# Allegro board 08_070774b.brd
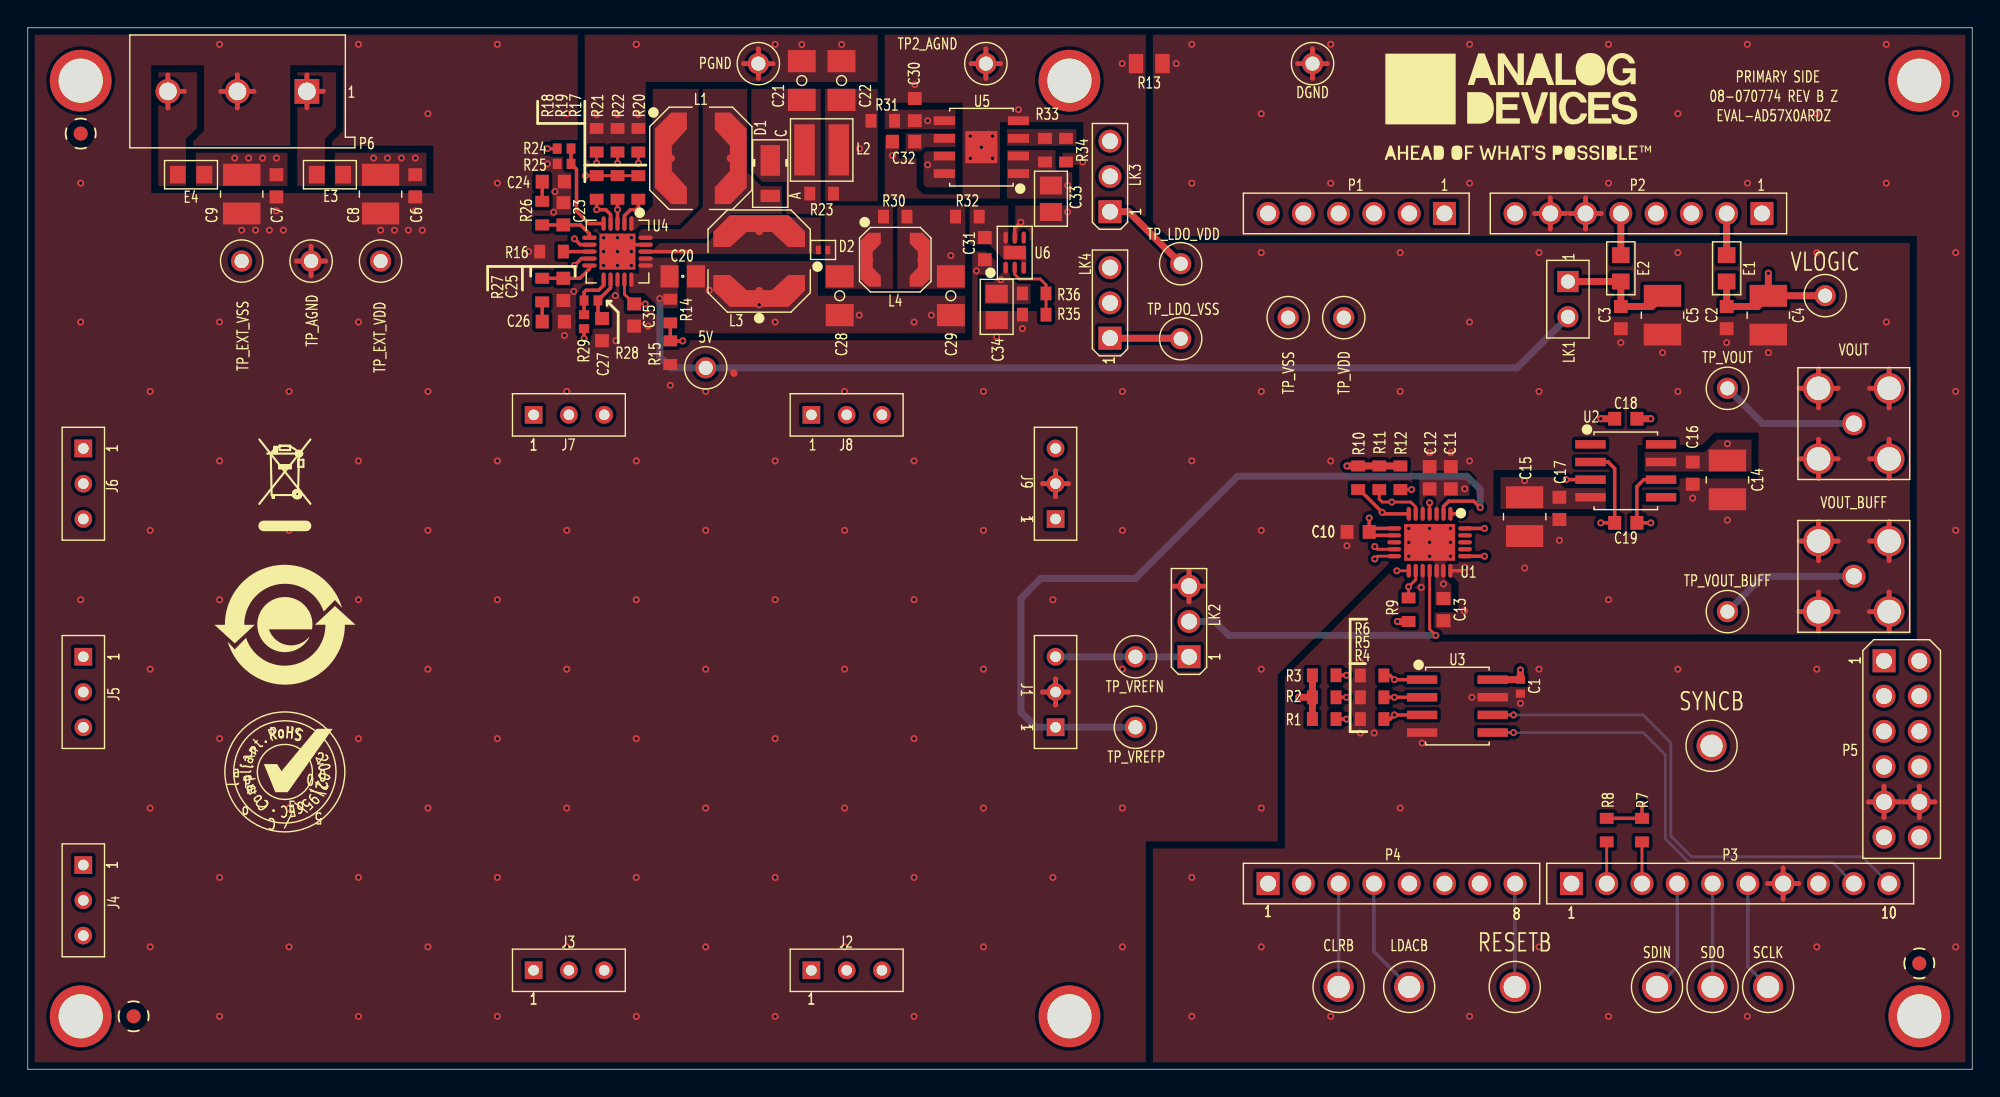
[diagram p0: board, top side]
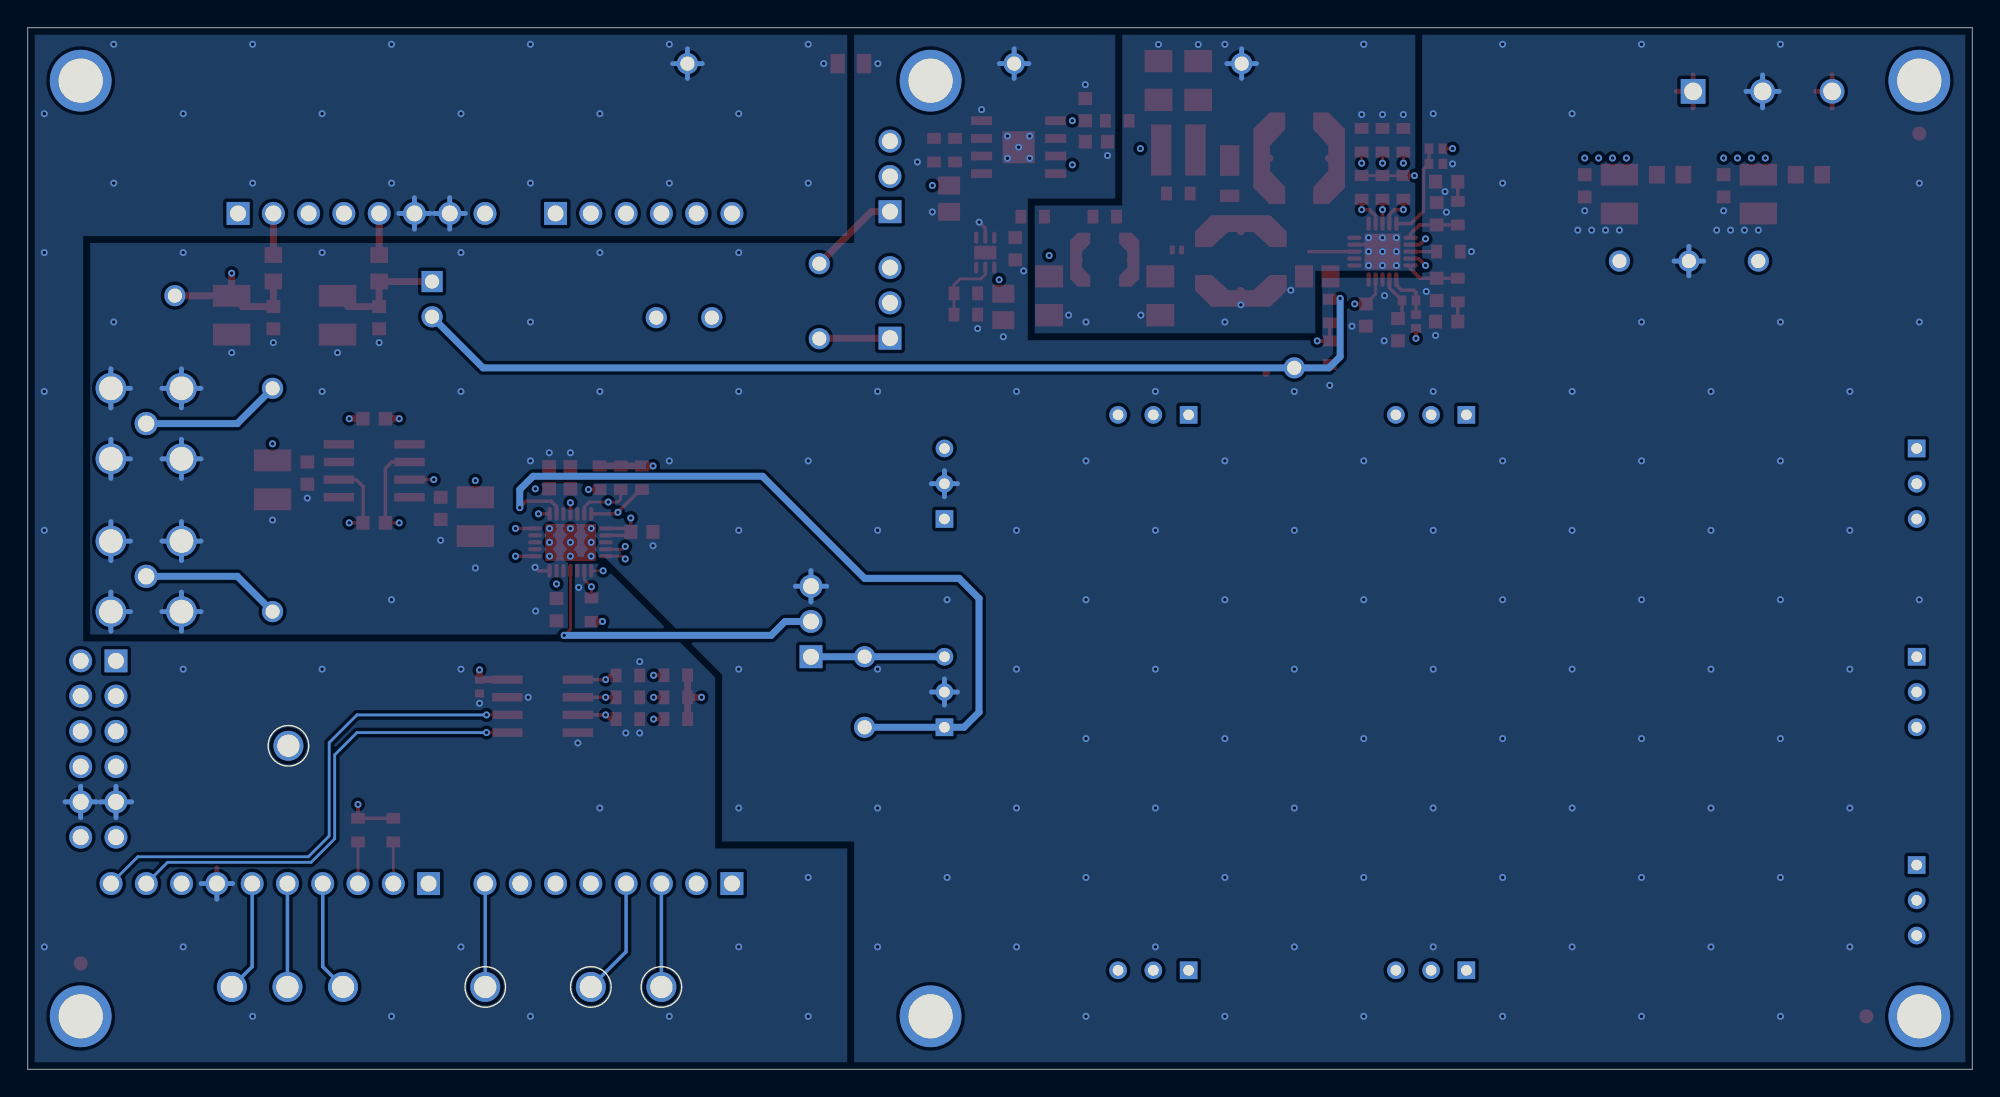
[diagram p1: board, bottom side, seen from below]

Outline 140 x 75 mm; copper layers: TOP, L2_GND, L3_SIG, L4_PWR, L5_GND, BOTTOM. Coordinates in mm from the lower left corner of the outline.
Outline path: 0,75 140,75 140,0 0,0 0,75

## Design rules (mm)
constraint set DEFAULT: 
net group POWER: nets AGND DGND VDD VSS

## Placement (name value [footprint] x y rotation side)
C1  0.1uF  [C0402]  107.47 27.55 90 top
C2  0.1uF  [C0603]  122.32 54.12 270 top
C3  0.1uF  [C0603]  114.7 54.12 270 top
C4  10uF  [C1210-2]  125.32 54.3 270 top
C5  10uF  [C1210-2]  117.7 54.3 270 top
C6  0.1uF  [C0603]  27.9 63.62 270 top
C7  0.1uF  [C0603]  17.9 63.62 270 top
C8  10uF  [C1210-2]  25.4 63.02 270 top
C9  10uF  [C1210-2]  15.4 63.02 270 top
C10  0.1uF  [C0603]  95.78 38.7 180 top
C11  0.1uF  [C0603]  102.46 42.59 90 top
C12  0.1uF  [C0603]  100.93 42.59 90 top
C13  0.1uF  [C0603]  101.93 33.09 270 top
C14  10uF  [C1210-2]  122.38 42.45 270 top
C15  10uF  [C1210-2]  107.78 39.79 90 top
C16  0.1uF  [C0603]  119.88 42.93 270 top
C17  0.1uF  [C0603]  110.28 40.39 90 top
C18  0.1uF  [C0603]  115.06 46.84 180 top
C19  10pF  [C0603]  115.06 39.34 180 top
C20  10uF  [C0805H60]  47.16 57.1 0 top
C21  4.7uF  [C1206H71]  55.73 71.2 90 top
C22  4.7uF  [C1206H71]  58.59 71.2 90 top
C23  27pF  [C0603]  38.56 61.6 90 top
C24  0.022uF  [C0603]  37.84 63.92 0 top
C25  22pF  [C0603]  38.56 56.16 270 top
C26  0.082uF  [C0603]  37.84 53.84 0 top
C27  1uF  [C0603]  41.34 53.26 270 top
C28  2.2uF  [C1206H71]  58.46 55.7 270 top
C29  2.2uF  [C1206H71]  66.46 55.7 270 top
C30  1uF  [C0603]  63.86 69.11 90 top
C31  1uF  [C0603]  68.9 59.09 270 top
C32  0.01uF  [C0603]  63.06 66.8 180 top
C33  2.2uF  [C0805H53]  73.67 62.69 270 top
C34  2.2uF  [C0805H53]  69.76 54.9 270 top
C35  1uF  [C0603]  43.66 54.31 270 top
CLRB  WHT  [CNKEY5005-9TP]  94.38 5.93 0 top
D1  DFLS130-7  [POWERDI123]  53.46 64.5 270 top
D2  BAT54LPS  [DFN2_1X0_6]  57.26 59 0 top
DGND  BLK  [CNKEY5001TP]  92.5 72.42 0 top
E1  600OHM  [L0805H50]  122.32 57.68 270 top
E2  600OHM  [L0805H50]  114.7 57.68 270 top
E3  600OHM  [L0805H50]  21.75 64.42 0 top
E4  600OHM  [L0805H50]  11.75 64.42 0 top
J1  350-10-103-00-006000  [CNTHMHDR1X3L300W100H284]  74 24.62 90 top
J2  310-13-103-41-001000  [CNTHFHDR1X3L300W100H165]  56.42 7.12 0 top
J3  310-13-103-41-001000  [CNTHFHDR1X3L300W100H165]  36.42 7.12 0 top
J4  350-10-103-00-006000  [CNTHMHDR1X3L300W100H284]  4 14.71 270 top
J5  310-13-103-41-001000  [CNTHFHDR1X3L300W100H165]  4 29.7 270 top
J6  310-13-103-41-001000  [CNTHFHDR1X3L300W100H165]  4 44.71 270 top
J7  310-13-103-41-001000  [CNTHFHDR1X3L300W100H165]  36.42 47.12 0 top
J8  350-10-103-00-006000  [CNTHMHDR1X3L300W100H284]  56.42 47.12 0 top
J9  310-13-103-41-001000  [CNTHFHDR1X3L300W100H165]  74 39.62 90 top
L1  15uH  [LSMSQ236H138]  48.46 65.6 0 top
L2  1.5uH  [LSMSQ157H83]  57.16 66.2 0 top
L3  6.8uH  [LSMSQ236H138]  52.66 58.2 90 top
L4  2.2UH  [LSMSQ154H71_A]  62.46 58.3 0 top
LDACB  WHT  [CNKEY5005-9TP]  99.46 5.93 0 top
LK1  69157-102HLF  [CNBERG69157-102]  110.89 56.73 270 top
LK2  TSW-103-08-G-S  [CNBERG1X3H205LD36]  83.61 29.7 90 top
LK3  TSW-103-08-G-S  [CNBERG1X3H205LD36]  77.92 61.76 90 top
LK4  TSW-103-08-G-S  [CNBERG1X3H205LD36]  77.92 52.65 90 top
NOREF  -  []  18.51 21.41 0 top
NOREF#2  -  []  18.51 32.01 0 top
NOREF#3  -  []  3.81 3.81 0 top
NOREF#4  -  []  140 75 0 top
NOREF#5  -  []  107.31 69.31 0 top
NOREF#6  -  []  15 -82 0 top
NOREF#7  -  [unnamed#2]  3.81 71.19 0 top
NOREF#8  -  []  15 -82 0 top
NOREF#9  -  []  140 0 0 top
NOREF#10  -  []  36.42 47.12 180 top
NOREF#11  -  [unnamed#2]  136.19 3.81 0 top
NOREF#12  -  []  88.21 167.82 0 top
NOREF#13  -  []  -2.99 312.45 0 top
NOREF#14  -  [unnamed#2]  3.81 67.38 0 top
NOREF#15  -  [unnamed#2]  3.81 3.81 0 top
NOREF#16  -  []  0 0 0 top
NOREF#17  -  []  76.21 73.31 0 top
NOREF#18  -  []  -22.36 -50.33 0 top
NOREF#19  -  []  -10.17 228.03 0 top
NOREF#20  -  []  212.02 314.24 0 top
NOREF#21  -  []  140 0 90 top
NOREF#22  -  [unnamed#2]  136.19 71.19 0 top
NOREF#23  -  [unnamed#2]  75 3.81 0 top
NOREF#24  -  []  -22.36 -50.33 0 top
NOREF#25  -  []  3.81 3.81 0 top
NOREF#26  -  []  134 13.37 180 top
NOREF#27  -  [unnamed#2]  75 71.19 0 top
NOREF#28  -  []  18.31 38.81 0 top
NOREF#29  -  []  76.75 90.75 0 top
NOREF#30  -  []  0 75 0 top
NOREF#31  -  [unnamed#2]  7.62 3.81 0 top
NOREF#32  -  []  140 0 0 top
NOREF#33  -  [unnamed#2]  136.19 7.62 0 top
P1  SSQ-106-03-G-S  [CNSAMTECSSQ-106-XX-X-S]  102 61.63 180 top
P2  SSQ-108-03-G-S  [CNSAMTECSSQ-108-XX-X-S]  124.86 61.63 180 top
P3  SSQ-110-03-G-S  [CNSAMTECSSQ-110-XX-X-S]  111.14 13.37 0 top
P4  SSQ-108-03-G-S  [CNSAMTECSSQ-108-XX-X-S]  89.3 13.37 0 top
P5  TSW-106-08-G-D  [CNHDR2X6H330LD35]  133.65 29.41 270 top
P6  8719  [CNKEYSTONE-8719]  20.1 70.42 180 top
PGND  BLK  [CNKEY5001TP]  52.6 72.42 0 top
R1  100K  [R0603]  93.34 25.21 0 top
R2  0  [R0603]  93.34 26.79 0 top
R3  0  [R0603]  93.34 28.37 0 top
R4  0  [R0603]  96.79 25.21 180 top
R5  100K  [R0603]  96.79 26.79 180 top
R6  100K  [R0603]  96.79 28.36 180 top
R7  0  [R0603]  116.22 17.22 90 top
R8  0  [R0603]  113.68 17.22 90 top
R9  10K  [R0603]  99.42 33.09 90 top
R10  10K  [R0603]  95.78 42.59 270 top
R11  10K  [R0603]  97.31 42.59 270 top
R12  10K  [R0603]  98.83 42.59 270 top
R13  0  [R0805]  80.74 72.42 180 top
R14  30.1K  [R0603]  46.26 54.6 90 top
R15  18.7K  [R0603]  46.26 51.6 90 top
R16  49.9K  [R0603]  37.71 58.88 0 top
R17  0  [R0603]  43.96 63.5 270 top
R18  0  [R0603]  40.96 63.5 270 top
R19  0  [R0603]  42.46 63.5 270 top
R20  0  [R0603]  43.96 66.9 90 top
R21  0  [R0603]  40.96 66.9 90 top
R22  0  [R0603]  42.46 66.9 90 top
R23  4.7  [R0603]  57.16 63.06 0 top
R24  63.4K  [R0402]  38.62 66.3 180 top
R25  3.57K  [R0402]  38.62 65.2 180 top
R26  22K  [R0603]  37.04 61.65 90 top
R27  30.1K  [R0603]  37.04 56.11 270 top
R28  2.8K  [R0402]  40.55 55.36 180 top
R29  54.9K  [R0402]  40.05 53.84 270 top
R30  10  [R0603]  62.46 61.4 0 top
R31  10  [R0603]  61.56 68.31 0 top
R32  10  [R0603]  67.65 61.4 0 top
R33  105K  [R0603]  73.24 66.19 90 top
R34  10K  [R0603]  74.75 66.19 270 top
R35  10K  [R0603]  72.46 54.34 0 top
R36  105K  [R0603]  72.46 55.87 180 top
RESETB  WHT  [CNKEY5005-9TP]  107.06 5.93 0 top
SCLK  WHT  [CNKEY5005-9TP]  125.3 5.93 0 top
SDIN  WHT  [CNKEY5005-9TP]  117.3 5.93 0 top
SDO  WHT  [CNKEY5005-9TP]  121.3 5.93 0 top
SYNCB  WHT  [CNKEY5005-9TP]  121.23 23.29 0 top
TP2_AGND  BLK  [CNKEY5001TP]  68.98 72.42 0 top
TP_AGND  BLK  [CNKEY5001TP]  20.4 58.2 0 top
TP_EXT_VDD  RED  [CNKEY5001TP]  25.4 58.2 0 top
TP_EXT_VSS  RED  [CNKEY5001TP]  15.4 58.2 0 top
TP_LDO_VDD  RED  [CNKEY5001TP]  83.01 58.01 0 top
TP_LDO_VSS  RED  [CNKEY5001TP]  83.01 52.61 0 top
TP_VDD  RED  [CNKEY5001TP]  94.75 54.12 0 top
TP_VOUT  RED  [CNKEY5001TP]  122.38 49.04 0 top
TP_VOUT_BUFF  RED  [CNKEY5001TP]  122.38 32.95 0 top
TP_VREFN  RED  [CNKEY5001TP]  79.75 29.7 0 top
TP_VREFP  RED  [CNKEY5001TP]  79.75 24.62 0 top
TP_VSS  RED  [CNKEY5001TP]  90.75 54.12 0 top
U1  AD5780BCPZ  [QFN24_5X4_PAD3_65X2_65]  100.93 37.95 180 top
U2  AD8675ARZ  [SO8]  115.06 43.09 270 top
U3  24AA32A-I/SN  [SO8]  102.93 26.15 270 top
U4  ADP5070ACPZ-R7  [QFN20_4X4_PAD2_6X2_6]  42.46 58.88 180 top
U5  ADP7118ARDZ  [SO8NB-PAD2_3X2_3]  68.66 66.4 90 top
U6  ADP7182ACPZN  [DFN6_2X2_PAD1_6X1]  71.06 58.81 0 top
UNK5V  RED  [CNKEY5001TP]  48.81 50.51 0 top
VLOGIC  RED  [CNKEY5001TP]  129.41 55.71 0 top
VOUT  131-3701-261  [CNJOHNSON131-3701-261]  131.47 46.5 0 top
VOUT_BUFF  131-3701-261  [CNJOHNSON131-3701-261]  131.47 35.49 0 top

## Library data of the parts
C1 = CAP: User Part Number: UPN; Tolerance: 10; alternate symbols: (C0402); part number: CAP_SM-0.1UF,16V,10,E028141,C0402; tolerance: 10
C2 C3 C6 C7 C10-C13 C16-C18 = CAP: User Part Number: UPN; Tolerance: 10; alternate symbols: (C0603); part number: CAP_SM-0.1UF,16V,10,E015036,C0603; tolerance: 10
C4 C5 C8 C9 C14 C15 = CAP: Tolerance: 10; User Part Number: UPN; alternate symbols: (C1210-2); part number: CAP_SM-10UF,50V,10,E022361,C1210-2; tolerance: 10
C19 = CAP: User Part Number: UPN; Tolerance: 0.5pF; alternate symbols: (C0603); part number: CAP_SM-10PF,50V,0.5PF,E016319,C0603; tolerance: 0.5pF
C20 = CAP: Tolerance: 10; User Part Number: UPN; alternate symbols: (C0805H60); part number: CAP_SM-10UF,25V,10,E026259,C0805H60; tolerance: 10
C21 C22 = CAP: Tolerance: 20; User Part Number: UPN; alternate symbols: (C1206H71); part number: CAP_SM-4.7UF,50V,20,E028522,C1206H71; tolerance: 20
C23 = CAP: User Part Number: UPN; Tolerance: 5; alternate symbols: (C0603); part number: CAP_SM-27PF,50V,5,E000395,C0603; tolerance: 5
C24 = CAP: User Part Number: UPN; Tolerance: 10; alternate symbols: (C0603); part number: CAP_SM-0.022UF,16V,10,E000327,C0603; tolerance: 10
C25 = CAP: User Part Number: UPN; Tolerance: 5; alternate symbols: (C0603); part number: CAP_SM-22PF,50V,5,E000411,C0603; tolerance: 5
C26 = CAP: User Part Number: UPN; Tolerance: 10; alternate symbols: (C0603); part number: CAP_SM-0.082UF,16V,10,E000332,C0603; tolerance: 10
C27 = CAP: User Part Number: UPN; Tolerance: 20; alternate symbols: (C0603); part number: CAP_SM-1UF,6.3V,20,E021364,C0603; tolerance: 20
C28 C29 = CAP: Tolerance: 10; User Part Number: UPN; alternate symbols: (C1206H71); part number: CAP_SM-2.2UF,50V,10,E033575,C1206H71; tolerance: 10
C30 C31 = CAP: User Part Number: UPN; Tolerance: 10; alternate symbols: (C0603); part number: CAP_SM-1UF,16V,10,E020596,C0603; tolerance: 10
C32 = CAP: User Part Number: UPN; Tolerance: 10; alternate symbols: (C0603); part number: CAP_SM-0.01UF,50V,10,E015579,C0603; tolerance: 10
C33 C34 = CAP: Tolerance: 10; User Part Number: UPN; alternate symbols: (C0805H53); part number: CAP_SM-2.2UF,25V,10,E025703,C0805H53; tolerance: 10
C35 = CAP: User Part Number: UPN; Tolerance: 10; alternate symbols: (C0603); part number: CAP_SM-1UF,16V,10,E025399,C0603; tolerance: 10
CLRB LDACB RESETB SCLK SDIN SDO SYNCB = CNTP1P: Tolerance: N/A; User Part Number: UPN; alternate symbols: (CNKEY5005-9TP); part number: CNTP1P_TH-WHT,E025331,CNKEY5005-9TP; tolerance: N/A
D1 = DIOSCHOTTKY: User Part Number: UPN; Tolerance: N/A; alternate symbols: (POWERDI123); part number: DIOSCHOTTKY_SM-DFLS130-7,30V,N/A,E026485,POWERDI123; tolerance: N/A
D2 = DIOSCHOTTKY: Tolerance: N/A; User Part Number: UPN; alternate symbols: (DFN2_1X0_6); part number: DIOSCHOTTKY_SM-BAT54LPS,30V,N/A,E023691,DFN2_1X0_6; tolerance: N/A
DGND PGND TP2_AGND TP_AGND = CNTP1P: Tolerance: N/A; User Part Number: UPN; alternate symbols: (CNKEY5001TP); part number: CNTP1P_TH-BLK,E005347,CNKEY5001TP; tolerance: N/A
E1-E4 = FERRITE: Tolerance: 25; User Part Number: UPN; alternate symbols: (L0805H50); part number: FERRITE_SM-600OHM,25,E013538,L0805H50; tolerance: 25
J1 J4 J8 = CN3P: User Part Number: UPN; Tolerance: N/A; alternate symbols: (CNTHMHDR1X3L300W100H284); part number: CN3P_TH-350-10-103-00-006000,E027762,CNTHMHDR1X3L300W100H284; tolerance: N/A
J2 J3 J5-J7 J9 = CN3P: User Part Number: UPN; Tolerance: N/A; alternate symbols: (CNTHFHDR1X3L300W100H165); part number: CN3P_TH-310-13-103-41-001000,E027752,CNTHFHDR1X3L300W100H165; tolerance: N/A
L1 = IND: User Part Number: UPN; Tolerance: 20; alternate symbols: (LSMSQ236H138); part number: IND_SM-15UH,20,E019587,LSMSQ236H138; tolerance: 20
L2 = IND: User Part Number: UPN; Tolerance: 20; alternate symbols: (LSMSQ157H83); part number: IND_SM-1.5UH,20,E017267,LSMSQ157H83; tolerance: 20
L3 = IND: User Part Number: UPN; Tolerance: 20; alternate symbols: (LSMSQ236H138); part number: IND_SM-6.8UH,20,E020918,LSMSQ236H138; tolerance: 20
L4 = IND: User Part Number: UPN; Tolerance: 20; alternate symbols: (LSMSQ154H71_A); part number: IND_SM-2.2UH,20,E024446,LSMSQ154H71_A; tolerance: 20
LK1 = CN2P: User Part Number: UPN; Tolerance: N/A; alternate symbols: (CNBERG69157-102); part number: CN2P_TH-69157-102HLF,E000791,CNBERG69157-102; tolerance: N/A
LK2-LK4 = CN3P: User Part Number: UPN; Tolerance: N/A; alternate symbols: (CNBERG1X3H205LD36); part number: CN3P_TH-TSW-103-08-G-S,E000812,CNBERG1X3H205LD36; tolerance: N/A
P1 = CN6P: User Part Number: UPN; Tolerance: N/A; alternate symbols: (CNSAMTECSSQ-106-XX-X-S); part number: CN6P_TH-SSQ-106-03-G-S,E020477,CNSAMTECSSQ-106-XX-X-S; tolerance: N/A
P2 P4 = CN8P_A: User Part Number: UPN; Tolerance: N/A; alternate symbols: (CNSAMTECSSQ-108-XX-X-S); part number: CN8P_A_TH-SSQ-108-03-G-S,E020478,CNSAMTECSSQ-108-XX-X-S; tolerance: N/A
P3 = CN10P: User Part Number: UPN; Tolerance: N/A; alternate symbols: (CNSAMTECSSQ-110-XX-X-S); part number: CN10P_TH-SSQ-110-03-G-S,E020479,CNSAMTECSSQ-110-XX-X-S; tolerance: N/A
P5 = CN12P_V3: Tolerance: N/A; User Part Number: UPN; alternate symbols: (CNHDR2X6H330LD35); part number: CN12P_V3_TH-TSW-106-08-G-D,E000735,CNHDR2X6H330LD35; tolerance: N/A
P6 = CN3P: Tolerance: N/A; User Part Number: UPN; alternate symbols: (CNKEYSTONE-8719); part number: CN3P_TH-8719,E023615,CNKEYSTONE-8719; tolerance: N/A
R1 R5 R6 = RES: User Part Number: UPN; Tolerance: 1; alternate symbols: (R0603); part number: RES_SM-100K,E017869,1/10W,1,R0603; tolerance: 1
R2-R4 = RES: User Part Number: UPN; Tolerance: 1; alternate symbols: (R0603); part number: RES_SM-0,E004207,1/16W,1,R0603; tolerance: 1
R7 R8 R17-R22 = RES: User Part Number: UPN; Tolerance: JUMPER; alternate symbols: (R0603); part number: RES_SM-0,E054377,1/10W,JUMPER,R0603; tolerance: JUMPER
R9-R12 = RES: User Part Number: UPN; Tolerance: 0.01; alternate symbols: (R0603); part number: RES_SM-10K,E025505,1/16W,0.01,R0603; tolerance: 0.01
R13 = RES: User Part Number: UPN; Tolerance: N/A; alternate symbols: (R0805); part number: RES_SM-0,E030624,1/8W,N/A,R0805; tolerance: N/A
R14 R27 = RES: User Part Number: UPN; Tolerance: 1; alternate symbols: (R0603); part number: RES_SM-30.1K,E011129,1/10W,1,R0603; tolerance: 1
R15 = RES: User Part Number: UPN; Tolerance: 1; alternate symbols: (R0603); part number: RES_SM-18.7K,E011248,1/10W,1,R0603; tolerance: 1
R16 = RES: User Part Number: UPN; Tolerance: 1; alternate symbols: (R0603); part number: RES_SM-49.9K,E015342,1/10W,1,R0603; tolerance: 1
R23 = RES: User Part Number: UPN; Tolerance: 1; alternate symbols: (R0603); part number: RES_SM-4.7,E003938,1/10W,1,R0603; tolerance: 1
R24 = RES: User Part Number: UPN; Tolerance: 1; alternate symbols: (R0402); part number: RES_SM-63.4K,E006803,1/10W,1,R0402; tolerance: 1
R25 = RES: User Part Number: UPN; Tolerance: 1; alternate symbols: (R0402); part number: RES_SM-3.57K,E007344,1/10W,1,R0402; tolerance: 1
R26 = RES: User Part Number: UPN; Tolerance: 1; alternate symbols: (R0603); part number: RES_SM-22K,E019090,1/10W,1,R0603; tolerance: 1
R28 = RES: User Part Number: UPN; Tolerance: 1; alternate symbols: (R0402); part number: RES_SM-2.8K,E012202,1/10W,1,R0402; tolerance: 1
R29 = RES: User Part Number: UPN; Tolerance: 1; alternate symbols: (R0402); part number: RES_SM-54.9K,E023190,1/10W,1,R0402; tolerance: 1
R30-R32 = RES: User Part Number: UPN; Tolerance: 1; alternate symbols: (R0603); part number: RES_SM-10,E003666,1/10W,1,R0603; tolerance: 1
R33 R36 = RES: User Part Number: UPN; Tolerance: 1; alternate symbols: (R0603); part number: RES_SM-105K,E019711,1/10W,1,R0603; tolerance: 1
R34 R35 = RES: User Part Number: UPN; Tolerance: 1; alternate symbols: (R0603); part number: RES_SM-10K,E003671,1/10W,1,R0603; tolerance: 1
TP_EXT_VDD TP_EXT_VSS TP_LDO_VDD TP_LDO_VSS TP_VDD TP_VOUT TP_VOUT_BUFF TP_VREFN TP_VREFP TP_VSS VLOGIC = CNTP1P: Tolerance: N/A; User Part Number: UPN; alternate symbols: (CNKEY5001TP); part number: CNTP1P_TH-RED,E016323,CNKEY5001TP; tolerance: N/A
U1 = AD5780: User Part Number: UPN; Tolerance: N/A; alternate symbols: (QFN24_5X4_PAD3_65X2_65); part number: AD5780_SM-AD5780BCPZ,E016043,QFN24_5X4_PAD3_65X2_65; tolerance: N/A
U2 = AD8675: Tolerance: N/A; User Part Number: UPN; alternate symbols: (SO8); part number: AD8675_SM-AD8675ARZ,E005913,SO8; tolerance: N/A
U3 = IC24XX32A_V2: Tolerance: N/A; User Part Number: UPN; alternate symbols: (SO8); part number: IC24XX32A_V2_SM-24AA32A-I/SN,E034913,SO8; tolerance: N/A
U4 = ADP5070: User Part Number: UPN; Tolerance: N/A; alternate symbols: (QFN20_4X4_PAD2_6X2_6); part number: ADP5070_SM-ADP5070ACPZ-R7,E017319,QFN20_4X4_PAD2_6X2_6; tolerance: N/A
U5 = ADP7118_V3: Tolerance: N/A; User Part Number: UPN; alternate symbols: (SO8NB-PAD2_3X2_3); part number: ADP7118_V3_SM-ADP7118ARDZ,E020780,SO8NB-PAD2_3X2_3; tolerance: N/A
U6 = ADP7182_V5: User Part Number: UPN; Tolerance: N/A; alternate symbols: (DFN6_2X2_PAD1_6X1); part number: ADP7182_V5_SM-ADP7182ACPZN,E024308,DFN6_2X2_PAD1_6X1; tolerance: N/A
UNK5V = CNTP1P: Tolerance: N/A; User Part Number: UPN; alternate symbols: (CNKEY5001TP); part number: CNTP1P_TH-RED,E019485,CNKEY5001TP; tolerance: N/A
VOUT VOUT_BUFF = CNBNC5P: Tolerance: N/A; User Part Number: UPN; alternate symbols: (CNJOHNSON131-3701-261); part number: CNBNC5P_TH-131-3701-261,E012123,CNJOHNSON131-3701-261; tolerance: N/A

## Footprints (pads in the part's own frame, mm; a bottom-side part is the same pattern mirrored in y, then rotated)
C0402
  rect 0.584x0.66 smd: 1(-0.5,0) 2(0.5,0)
C0603
  rect 0.94x0.991 smd: 1(-0.8,0) 2(0.8,0)
C0805H53
  rect 1.295x1.6 smd: 1(-0.953,0) 2(0.953,0)
C0805H60
  rect 1.295x1.6 smd: 1(-0.953,0) 2(0.953,0)
C1206H71
  rect 1.6x2.007 smd: 1(-1.397,0) 2(1.397,0)
C1210-2
  rect 1.575x2.692 smd: 1(-1.397,0) 2(1.397,0)
CNBERG1X3H205LD36
  rect 1.651x1.651 hole 1.143: 1(0,0)
  round 1.651 hole 1.143: 2(2.54,0) 3(5.08,0)
CNBERG69157-102
  rect 1.524x1.524 hole 1.016: 1(0,0)
  round 1.524 hole 1.016: 2(2.54,0)
CNHDR2X6H330LD35
  rect 1.651x1.651 hole 1.143: 1(0,0)
  round 1.651 hole 1.143: 2(2.54,0) 3(5.08,0) 4(7.62,0) 5(10.16,0) 6(12.7,0) 7(0,2.54) 8(2.54,2.54) 9(5.08,2.54) 10(7.62,2.54) 11(10.16,2.54) 12(12.7,2.54)
CNJOHNSON131-3701-261
  round 1.676 hole 1.168: 1(0,0)
  round 2.21 hole 1.702: 2(-2.54,2.54) 3(2.54,2.54) 4(2.54,-2.54) 5(-2.54,-2.54)
CNKEY5001TP
  round 1.524 hole 1.016: 1(0,0)
CNKEY5005-9TP
  round 2.159 hole 1.6: 1(0,0)
CNKEYSTONE-8719
  rect 1.778x1.778 hole 1.27: 1(0,0)
  round 1.778 hole 1.27: 2(5.004,0) 3(10.008,0)
CNSAMTECSSQ-106-XX-X-S
  rect 1.651x1.651 hole 1.143: 1(0,0)
  round 1.651 hole 1.143: 2(2.54,0) 3(5.08,0) 4(7.62,0) 5(10.16,0) 6(12.7,0)
CNSAMTECSSQ-108-XX-X-S
  rect 1.651x1.651 hole 1.143: 1(0,0)
  round 1.651 hole 1.143: 2(2.54,0) 3(5.08,0) 4(7.62,0) 5(10.16,0) 6(12.7,0) 7(15.24,0) 8(17.78,0)
CNSAMTECSSQ-110-XX-X-S
  rect 1.651x1.651 hole 1.143: 1(0,0)
  round 1.651 hole 1.143: 2(2.54,0) 3(5.08,0) 4(7.62,0) 5(10.16,0) 6(12.7,0) 7(15.24,0) 8(17.78,0) 9(20.32,0) 10(22.86,0)
CNTHFHDR1X3L300W100H165
  rect 1.27x1.27 hole 0.762: 1(0,0)
  round 1.27 hole 0.762: 2(2.54,0) 3(5.08,0)
CNTHMHDR1X3L300W100H284
  rect 1.27x1.27 hole 0.762: 1(0,0)
  round 1.27 hole 0.762: 2(2.54,0) 3(5.08,0)
DFN2_1X0_6
  rect 0.356x0.61 smd: A(0.34,0) C(-0.34,0)
DFN6_2X2_PAD1_6X1
  oval 0.305x0.864 smd: 1(-0.65,-1.082) 2(0,-1.082) 3(0.65,-1.082) 4(0.65,1.082) 5(0,1.082) 6(-0.65,1.082)
  rect 1.6x0.991 smd: PAD(0,0)
L0805H50
  rect 1.143x1.27 smd: 1(-0.953,0) 2(0.953,0)
LSMSQ154H71_A
  custom 0.362x0.362 smd: 1(-1.765,0) 2(1.765,0)
LSMSQ157H83
  rect 1.473x3.683 smd: 1(-1.232,0) 2(1.232,0)
LSMSQ236H138
  custom 0.575x0.575 smd: 1(-2.151,0) 2(2.151,0)
POWERDI123
  rect 0.889x1.397 smd: A(1.605,0)
  rect 2.21x1.397 smd: C(-0.945,0)
QFN20_4X4_PAD2_6X2_6
  oval 0.305x1.041 smd: 1(-1,-2.019) 2(-0.5,-2.019) 3(0,-2.019) 4(0.5,-2.019) 5(1,-2.019) 11(1,2.019) 12(0.5,2.019) 13(0,2.019) 14(-0.5,2.019) 15(-1,2.019)
  oval 1.041x0.305 smd: 6(2.019,-1) 7(2.019,-0.5) 8(2.019,0) 9(2.019,0.5) 10(2.019,1) 16(-2.019,1) 17(-2.019,0.5) 18(-2.019,0) 19(-2.019,-0.5) 20(-2.019,-1)
  rect 2.591x2.591 smd: PAD(0,0)
QFN24_5X4_PAD3_65X2_65
  oval 0.305x0.991 smd: 1(-1.5,-2.05) 2(-1,-2.05) 3(-0.5,-2.05) 4(0,-2.05) 5(0.5,-2.05) 6(1,-2.05) 7(1.5,-2.05) 13(1.5,2.05) 14(1,2.05) 15(0.5,2.05) 16(0,2.05) 17(-0.5,2.05) 18(-1,2.05) 19(-1.5,2.05)
  oval 0.991x0.305 smd: 8(2.55,-1) 9(2.55,-0.5) 10(2.55,0) 11(2.55,0.5) 12(2.55,1) 20(-2.55,1) 21(-2.55,0.5) 22(-2.55,0) 23(-2.55,-0.5) 24(-2.55,-1)
  rect 3.658x2.642 smd: PAD(0,0)
R0402
  rect 0.635x0.737 smd: 1(-0.5,0) 2(0.5,0)
R0603
  rect 0.787x0.991 smd: 1(-0.85,0) 2(0.85,0)
R0805
  rect 1.041x1.397 smd: 1(-0.95,0) 2(0.95,0)
SO8
  rect 0.61x2.184 smd: 1(-1.905,-2.54) 2(-0.635,-2.54) 3(0.635,-2.54) 4(1.905,-2.54) 5(1.905,2.54) 6(0.635,2.54) 7(-0.635,2.54) 8(-1.905,2.54)
SO8NB-PAD2_3X2_3
  rect 0.635x1.524 smd: 1(-1.905,-2.667) 2(-0.635,-2.667) 3(0.635,-2.667) 4(1.905,-2.667) 5(1.905,2.667) 6(0.635,2.667) 7(-0.635,2.667) 8(-1.905,2.667)
  rect 2.311x2.311 smd: PAD(0,0)
unnamed#2
  round 4.445 hole 3.175 unplated: (0,0)

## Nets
AGND: C2.2(N2) C3.2(N2) C4.2(N2) C5.2(N2) C6.2(N2) C7.2(N2) C8.2(N2) C9.2(N2) C10.2(N2) C11.2(N2) C12.2(N2) C13.2(N2) C14.2(N2) C15.1 C16.2(N2) C17.1 C20.2(N2) C21.2(N2) C22.2(N2) C23.2(N2) C24.2(N2) C25.2(N2) C26.2(N2) C27.2(N2) C28.2(N2) C29.2(N2) C30.2(N2) C31.2(N2) C32.2(N2) C33.2(N2) C34.2(N2) C35.2(N2) J1.2 J9.2 L3.1 LK2.3(N3) P6.2 PGND.1(N1) R13.2(N2) R15.1 R16.1 R20.2(N2) R21.2(N2) R22.2(N2) R25.2(N2) R34.2(N2) R35.1 TP2_AGND.1(N1) TP_AGND.1(N1) U1.19 U4.13 U4.19 U4.PAD U5.4 U5.PAD U6.5 VOUT.2 VOUT.3 VOUT.4 VOUT.5(SH4) VOUT_BUFF.2 VOUT_BUFF.3 VOUT_BUFF.4 VOUT_BUFF.5(SH4)
DGND: C1.1 DGND.1(N1) P2.6 P2.7 P3.7 P5.5 P5.11 R4.2(N2) R5.2(N2) R6.2(N2) R13.1 U1.15 U3.4 U3.7(WP)
VDD: C11.1 C12.1 C14.1 C16.1 C18.1 J9.1 LK3.2 TP_VDD.1(N1) U1.3 U1.5 U2.7
VSS: C13.1 C15.2(N2) C17.2(N2) C18.2(N2) J9.3(N3) LK4.2 TP_VSS.1(N1) U1.17 U1.18(VSS2) U1.PAD U2.4(V-)
ARD_5V: C20.1 LK1.2(N2) R14.2(N2) U4.15 U4.16 U4.17 UNK5V.1
ARD_CLRB: CLRB.1(N1) P4.3 P5.9 R11.2(N2) U1.6
ARD_LDACB: LDACB.1(N1) P4.4 P5.7 R10.2(N2) U1.7
ARD_RESETB: P4.8(N8) P5.8 R12.2(N2) RESETB.1(N1) U1.4
ARD_SCL: P3.10 U3.6
ARD_SCLK: P3.6 P5.4 SCLK.1(N1) U1.13
ARD_SDA: P3.9(N9) U3.5
ARD_SDIN: P3.4 P5.2 SDIN.1(N1) U1.12
ARD_SDO: P3.5 P5.3 SDO.1(N1) U1.11
ARD_SYNCB: P5.1 R7.2(N2) R8.2(N2) R9.2(N2) SYNCB.1(N1) U1.14
ARD_VLOGIC: C1.2(N2) C2.1 C4.1 C10.1 E1.2(N2) P5.6 P5.12(VCC2) R1.1 R2.1 R3.1 R9.1 R10.1 R11.1 R12.1 U1.8 U1.9 U3.8 VLOGIC.1(N1)
DAC_INV: C19.2(N2) U1.24 U2.2
DAC_VOUT: C19.1 TP_VOUT_BUFF.1(N1) U1.20 U2.6 VOUT_BUFF.1
EXT_VDD: C6.1 C8.1 E3.2(N2) LK3.3(N3) TP_EXT_VDD.1(N1)
EXT_VSS: C7.1 C9.1 E4.2(N2) LK4.3(N3) TP_EXT_VSS.1(N1)
LDO_VDD: C33.1 LK3.1 R33.1 TP_LDO_VDD.1(N1) U5.1 U5.2(VOUT2)
LDO_VSS: C34.1 LK4.1 R36.2(N2) TP_LDO_VSS.1(N1) U6.1(VOUT)
REF_VREFN: J1.3(N3) LK2.1 TP_VREFN.1(N1)
REF_VREFP: J1.1 TP_VREFP.1(N1) U1.2
UNNAMED_3_CAP_I71_N1: C3.1 C5.1 E2.2(N2) LK1.1
UNNAMED_3_CN8PA_I4_N2: E1.1 P2.2
UNNAMED_3_CN8PA_I4_N5: E2.1 P2.5
UNNAMED_3_CN10P_I1_N2: P3.2 R8.1
UNNAMED_3_CN10P_I1_N3: P3.3 R7.1
UNNAMED_3_IC24XX32AV2_I22_A0: R3.2(N2) R6.1 U3.1
UNNAMED_3_IC24XX32AV2_I22_A1: R2.2(N2) R5.1 U3.2
UNNAMED_3_IC24XX32AV2_I22_A2: R1.2(N2) R4.1 U3.3
UNNAMED_4_AD5780_I104_VOUT: TP_VOUT.1(N1) U1.1 U2.3 VOUT.1
UNNAMED_4_AD5780_I104_VREFN: LK2.2 U1.16
UNNAMED_5_ADP5070_I73_COMP1: C23.1 R26.1 U4.6
UNNAMED_5_ADP5070_I73_COMP2: C25.1 R27.1 U4.10
UNNAMED_5_ADP5070_I73_EN1: R14.1 R15.2(N2) U4.7 U4.9
UNNAMED_5_ADP5070_I73_FB1: R24.1 R25.1 U4.5
UNNAMED_5_ADP5070_I73_FB2: R28.2(N2) R29.1 U4.11
UNNAMED_5_ADP5070_I73_INBK: L1.1 U4.1
UNNAMED_5_ADP5070_I73_SEQ: R19.2(N2) R22.1 U4.3
UNNAMED_5_ADP5070_I73_SLEW: R18.2(N2) R21.1 U4.4
UNNAMED_5_ADP5070_I73_SS: R16.2(N2) U4.8
UNNAMED_5_ADP5070_I73_SW1: D1.A(P) L1.2(N2) U4.20
UNNAMED_5_ADP5070_I73_SW2: D2.C L3.2(N2) U4.18
UNNAMED_5_ADP5070_I73_SYNC: R17.2(N2) R20.1 U4.2
UNNAMED_5_ADP5070_I73_VREF: C27.1 R28.1 U4.12
UNNAMED_5_ADP5070_I73_VREG: C35.1 R17.1 R18.1 R19.1 U4.14(VREG)
UNNAMED_5_ADP7118V3_I134_EN: C30.1 R31.2(N2) U5.5 U5.7 U5.8
UNNAMED_5_ADP7118V3_I134_SENSE: R33.2(N2) R34.1 U5.3
UNNAMED_5_ADP7118V3_I134_SS: C32.1 U5.6
UNNAMED_5_ADP7182V5_I135_ADJ: R35.2(N2) R36.1 U6.2
UNNAMED_5_ADP7182V5_I135_EN: C31.1 R32.2(N2) U6.3 U6.6 U6.PAD
UNNAMED_5_CAP_I94_N1: C21.1 D1.C L2.1 R23.1
UNNAMED_5_CAP_I98_N1: C22.1 L2.2(N2) R23.2(N2) R24.2(N2) R31.1
UNNAMED_5_CAP_I106_N1: C24.1 R26.2(N2)
UNNAMED_5_CAP_I110_N1: C26.1 R27.2(N2)
UNNAMED_5_CAP_I117_N1: C28.1 D2.A(P) L4.1 R30.1
UNNAMED_5_CAP_I118_N1: C29.1 L4.2(N2) R29.2(N2) R30.2(N2) R32.1
UNNAMED_5_CN3P_I182_N1: E3.1 P6.1
UNNAMED_5_CN3P_I182_N3: E4.1 P6.3(N3)

Pads without a net: J2 1 2 3; J3 1 2 3; J4 1 2 3; J5 1 2 3; J6 1 2 3; J7 1 2 3; J8 1 2 3; P1 1 2 3 4 5 6; P2 1 3 4 8; P3 1 8; P4 1 2 5 6 7; P5 10; U1 10 21 22 23; U2 1 5 8; U6 4

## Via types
v1: diameter 0.508, hole 0.254, TOP to BOTTOM, 289 vias

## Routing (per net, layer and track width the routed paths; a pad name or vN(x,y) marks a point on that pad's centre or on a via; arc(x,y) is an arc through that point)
AGND: length 293
  TOP w0.25: U6.5 71.06,60.56 v1(71.5,61) ; v1(42.46,58.88) 42.96,59.38 U4.19 ; v1(103.48,36.15) 103.23,35.9 U1.19
  TOP w0.35: TP_AGND.1 21.46,58.2 ; TP_AGND.1 20.4,57.14 ; TP_AGND.1 20.4,59.26 ; TP_AGND.1 19.34,58.2 ; 132.61,38.04 VOUT_BUFF.3 ; VOUT_BUFF.3 134.01,36.63 ; VOUT_BUFF.3 134.01,39.44 ; 83.61,33.66 LK2.3 ; LK2.3 84.74,34.79 ; LK2.3 83.61,35.91 ; LK2.3 82.48,34.79 ; J9.2 74.94,42.16 ; J9.2 74,41.23 ; J9.2 73.06,42.16 ; J9.2 74,43.1 ; 67.92,72.42 TP2_AGND.1 ; TP2_AGND.1 70.05,72.42 ; TP2_AGND.1 68.98,73.48 ; TP2_AGND.1 68.98,71.36 ; J1.2 74.94,27.16 ; J1.2 74,28.1 ; J1.2 73.06,27.16 ; J1.2 74,26.23 ; P6.2 16.28,70.42 ; P6.2 13.9,70.42 ; P6.2 15.09,69.23 ; P6.2 15.09,71.61 ; 128.93,42.55 VOUT.5 ; VOUT.5 130.34,43.96 ; VOUT.5 127.53,43.96 ; VOUT.5 128.93,45.36 ; VOUT_BUFF.5 130.34,32.95 ; VOUT_BUFF.5 128.93,34.36 ; VOUT_BUFF.5 128.93,31.55 ; VOUT_BUFF.5 127.53,32.95 ; PGND.1 52.6,73.48 ; PGND.1 52.6,71.36 ; PGND.1 53.66,72.42 ; PGND.1 51.54,72.42 ; VOUT.2 128.93,50.44 ; VOUT.2 130.34,49.04 ; VOUT.2 127.53,49.04 ; VOUT.2 128.93,47.63 ; 127.53,38.04 VOUT_BUFF.2 ; VOUT_BUFF.2 128.93,36.63 ; VOUT_BUFF.2 128.93,39.44 ; VOUT_BUFF.2 130.34,38.04 ; VOUT.3 134.01,50.44 ; VOUT.3 134.01,47.63 ; VOUT.3 132.61,49.04 ; 134.01,31.55 VOUT_BUFF.4 ; VOUT_BUFF.4 132.61,32.95 ; VOUT_BUFF.4 134.01,34.36 ; VOUT.4 134.01,45.36 ; VOUT.4 134.01,42.55 ; VOUT.4 132.61,43.96
  TOP w0.5: 50.86,50.11 50.81,50.16
  L2_GND w0.35: P6.2 15.09,71.61 ; P6.2 13.9,70.42 ; P6.2 15.09,69.23 ; P6.2 16.28,70.42 ; J1.2 74.94,27.16 ; J1.2 74,26.23 ; J1.2 74,28.1 ; J1.2 73.06,27.16 ; 52.6,71.36 PGND.1 ; PGND.1 53.66,72.42 ; PGND.1 51.54,72.42 ; PGND.1 52.6,73.48 ; 132.61,43.96 VOUT.4 ; VOUT.4 134.01,45.36 ; VOUT.4 134.01,42.55 ; TP_AGND.1 20.4,59.26 ; TP_AGND.1 21.46,58.2 ; TP_AGND.1 20.4,57.14 ; TP_AGND.1 19.34,58.2 ; VOUT_BUFF.5 128.93,34.36 ; VOUT_BUFF.5 127.53,32.95 ; VOUT_BUFF.5 128.93,31.55 ; VOUT_BUFF.5 130.34,32.95 ; 67.92,72.42 TP2_AGND.1 ; TP2_AGND.1 68.98,71.36 ; TP2_AGND.1 68.98,73.48 ; TP2_AGND.1 70.05,72.42 ; 73.06,42.16 J9.2 ; J9.2 74,43.1 ; J9.2 74.94,42.16 ; J9.2 74,41.23 ; 127.53,49.04 VOUT.2 ; VOUT.2 128.93,47.63 ; VOUT.2 128.93,50.44 ; VOUT.2 130.34,49.04 ; 134.01,31.55 VOUT_BUFF.4 ; VOUT_BUFF.4 132.61,32.95 ; VOUT_BUFF.4 134.01,34.36 ; VOUT_BUFF.3 134.01,39.44 ; VOUT_BUFF.3 132.61,38.04 ; VOUT_BUFF.3 134.01,36.63 ; 127.53,43.96 VOUT.5 ; VOUT.5 128.93,45.36 ; VOUT.5 130.34,43.96 ; VOUT.5 128.93,42.55 ; 134.01,47.63 VOUT.3 ; VOUT.3 132.61,49.04 ; VOUT.3 134.01,50.44 ; 83.61,33.66 LK2.3 ; LK2.3 82.48,34.79 ; LK2.3 83.61,35.91 ; LK2.3 84.74,34.79 ; 128.93,36.63 VOUT_BUFF.2 ; VOUT_BUFF.2 128.93,39.44 ; VOUT_BUFF.2 127.53,38.04 ; VOUT_BUFF.2 130.34,38.04
  L4_PWR w0.35: TP_AGND.1 21.46,58.2 ; TP_AGND.1 20.4,57.14 ; TP_AGND.1 20.4,59.26 ; TP_AGND.1 19.34,58.2 ; J1.2 74.94,27.16 ; J1.2 74,26.23 ; J1.2 73.06,27.16 ; J1.2 74,28.1 ; 15.09,69.23 P6.2 ; P6.2 13.9,70.42 ; P6.2 15.09,71.61 ; P6.2 16.28,70.42
  L5_GND w0.35: VOUT_BUFF.3 134.01,39.44 ; VOUT_BUFF.3 134.01,36.63 ; VOUT_BUFF.3 132.61,38.04 ; VOUT_BUFF.5 130.34,32.95 ; VOUT_BUFF.5 127.53,32.95 ; VOUT_BUFF.5 128.93,31.55 ; VOUT_BUFF.5 128.93,34.36 ; 132.61,32.95 VOUT_BUFF.4 ; VOUT_BUFF.4 134.01,34.36 ; VOUT_BUFF.4 134.01,31.55 ; PGND.1 53.66,72.42 ; PGND.1 51.54,72.42 ; PGND.1 52.6,73.48 ; PGND.1 52.6,71.36 ; 128.93,42.55 VOUT.5 ; VOUT.5 128.93,45.36 ; VOUT.5 127.53,43.96 ; VOUT.5 130.34,43.96 ; 132.61,43.96 VOUT.4 ; VOUT.4 134.01,42.55 ; VOUT.4 134.01,45.36 ; TP2_AGND.1 68.98,73.48 ; TP2_AGND.1 67.92,72.42 ; TP2_AGND.1 70.05,72.42 ; TP2_AGND.1 68.98,71.36 ; J9.2 74.94,42.16 ; J9.2 74,43.1 ; J9.2 74,41.23 ; J9.2 73.06,42.16 ; 13.9,70.42 P6.2 ; P6.2 15.09,69.23 ; P6.2 16.28,70.42 ; P6.2 15.09,71.61 ; 134.01,47.63 VOUT.3 ; VOUT.3 132.61,49.04 ; VOUT.3 134.01,50.44 ; LK2.3 84.74,34.79 ; LK2.3 83.61,33.66 ; LK2.3 82.48,34.79 ; LK2.3 83.61,35.91 ; TP_AGND.1 20.4,59.26 ; TP_AGND.1 19.34,58.2 ; TP_AGND.1 21.46,58.2 ; TP_AGND.1 20.4,57.14 ; 128.93,36.63 VOUT_BUFF.2 ; VOUT_BUFF.2 128.93,39.44 ; VOUT_BUFF.2 130.34,38.04 ; VOUT_BUFF.2 127.53,38.04 ; 128.93,47.63 VOUT.2 ; VOUT.2 127.53,49.04 ; VOUT.2 128.93,50.44 ; VOUT.2 130.34,49.04 ; 73.06,27.16 J1.2 ; J1.2 74,28.1 ; J1.2 74,26.23 ; J1.2 74.94,27.16
  BOTTOM w0.35: TP2_AGND.1 70.05,72.42 ; TP2_AGND.1 67.92,72.42 ; TP2_AGND.1 68.98,71.36 ; TP2_AGND.1 68.98,73.48 ; VOUT_BUFF.3 134.01,39.44 ; VOUT_BUFF.3 132.61,38.04 ; VOUT_BUFF.3 134.01,36.63 ; J9.2 74.94,42.16 ; J9.2 74,43.1 ; J9.2 74,41.23 ; J9.2 73.06,42.16 ; VOUT.2 130.34,49.04 ; VOUT.2 128.93,47.63 ; VOUT.2 128.93,50.44 ; VOUT.2 127.53,49.04 ; VOUT_BUFF.4 134.01,34.36 ; VOUT_BUFF.4 134.01,31.55 ; VOUT_BUFF.4 132.61,32.95 ; VOUT.5 128.93,45.36 ; VOUT.5 128.93,42.55 ; VOUT.5 127.53,43.96 ; VOUT.5 130.34,43.96 ; VOUT_BUFF.5 130.34,32.95 ; VOUT_BUFF.5 127.53,32.95 ; VOUT_BUFF.5 128.93,34.36 ; VOUT_BUFF.5 128.93,31.55 ; 13.9,70.42 P6.2 ; P6.2 16.28,70.42 ; P6.2 15.09,69.23 ; P6.2 15.09,71.61 ; 127.53,38.04 VOUT_BUFF.2 ; VOUT_BUFF.2 128.93,39.44 ; VOUT_BUFF.2 130.34,38.04 ; VOUT_BUFF.2 128.93,36.63 ; LK2.3 84.74,34.79 ; LK2.3 83.61,35.91 ; LK2.3 83.61,33.66 ; LK2.3 82.48,34.79 ; 51.54,72.42 PGND.1 ; PGND.1 53.66,72.42 ; PGND.1 52.6,71.36 ; PGND.1 52.6,73.48 ; VOUT.4 134.01,45.36 ; VOUT.4 132.61,43.96 ; VOUT.4 134.01,42.55 ; 19.34,58.2 TP_AGND.1 ; TP_AGND.1 21.46,58.2 ; TP_AGND.1 20.4,57.14 ; TP_AGND.1 20.4,59.26 ; 134.01,47.63 VOUT.3 ; VOUT.3 132.61,49.04 ; VOUT.3 134.01,50.44 ; 74,26.23 J1.2 ; J1.2 73.06,27.16 ; J1.2 74.94,27.16 ; J1.2 74,28.1
  vias: v1(3.81,63.81) v1(3.81,53.81) v1(3.81,33.81) v1(8.81,48.81) v1(8.81,38.81) v1(8.81,28.81) v1(8.81,18.81) v1(8.81,8.81) v1(13.81,73.81) v1(13.81,53.81) v1(13.81,43.81) v1(13.81,33.81) v1(13.81,23.81) v1(13.81,13.81) v1(13.81,3.81) v1(15.4,60.43) v1(16.4,60.43) v1(17.4,60.43) v1(17.9,61.82) v1(18.4,60.43) v1(18.81,48.81) v1(18.81,38.81) v1(18.81,28.81) v1(18.81,18.81) v1(18.81,8.81) v1(23.81,73.81) v1(23.81,53.81) v1(23.81,43.81) v1(23.81,33.81) v1(23.81,23.81) v1(23.81,13.81) v1(23.81,3.81) v1(25.4,60.43) v1(26.4,60.43) v1(27.4,60.43) v1(27.9,61.82) v1(28.4,60.43) v1(28.81,68.81) v1(28.81,48.81) v1(28.81,38.81) v1(28.81,28.81) v1(28.81,18.81) v1(28.81,8.81) v1(33.81,73.81) v1(33.81,63.81) v1(33.81,43.81) v1(33.81,33.81) v1(33.81,23.81) v1(33.81,13.81) v1(33.81,3.81) v1(36.06,58.88) v1(37.41,65.2) v1(37.86,61.72) v1(37.96,63.2) v1(38.64,52.84) v1(38.81,68.81) v1(38.81,48.81) v1(38.81,38.81) v1(38.81,28.81) v1(38.81,18.81) v1(38.81,8.81) v1(39.31,56.01) v1(40.96,68.75) v1(41.46,59.88) v1(41.46,58.88) v1(41.46,57.88) v1(42.31,55.71) v1(42.34,52.46) v1(42.46,68.75) v1(42.46,59.88) v1(42.46,57.88) v1(43.46,59.88) v1(43.46,58.88) v1(43.46,57.88) v1(43.81,73.81) v1(43.81,73.81) v1(43.81,43.81) v1(43.81,33.81) v1(43.81,23.81) v1(43.81,13.81) v1(43.81,3.81) v1(43.96,68.75) v1(44.66,53.51) v1(46.26,49.25) v1(48.81,48.81) v1(48.81,38.81) v1(48.81,28.81) v1(48.81,18.81) v1(48.81,8.81) v1(49.06,56.1) v1(52.66,55.05) v1(53.81,73.81) v1(53.81,53.81) v1(53.81,43.81) v1(53.81,33.81) v1(53.81,23.81) v1(53.81,13.81) v1(53.81,3.81) v1(55.73,73.8) v1(58.59,73.8) v1(58.81,48.81) v1(58.81,38.81) v1(58.81,28.81) v1(58.81,18.81) v1(58.81,8.81) v1(59.86,54.3) v1(62.26,65.8) v1(63.86,70.91) v1(63.81,53.81) v1(63.81,43.81) v1(63.81,33.81) v1(63.81,23.81) v1(63.81,13.81) v1(63.81,3.81) v1(65.06,54.3) v1(67.86,67.2) v1(67.86,65.6) v1(68.3,57.49) v1(68.66,66.4) v1(68.81,48.81) v1(68.81,38.81) v1(68.81,28.81) v1(68.81,18.81) v1(68.81,8.81) v1(69.46,67.2) v1(69.46,65.6) v1(69.76,52.75) v1(71.33,69.11) v1(71.61,53.34) v1(73.81,33.81) v1(73.81,13.81) v1(74.87,61.74) v1(75.95,65.33) v1(78.79,72.42) v1(78.81,48.81) v1(78.81,38.81) v1(78.81,28.81) v1(78.81,18.81) v1(78.81,8.81) v1(83.81,43.81) v1(88.81,58.81) v1(88.81,48.81) v1(88.81,38.81) v1(88.81,28.81) v1(88.81,18.81) v1(93.81,43.81) v1(94.98,37.7) v1(98.81,58.81) v1(98.81,48.81) v1(100.93,44.4) v1(102.46,44.4) v1(103.43,32.99) v1(103.81,53.81) v1(103.81,43.81) v1(107.78,36.1) v1(108.81,58.81) v1(108.81,48.81) v1(110.28,38.09) v1(113.81,33.81) v1(114.7,52.33) v1(117.7,51.6) v1(118.81,58.81) v1(118.81,48.81) v1(119.88,41.13) v1(122.32,52.33) v1(122.38,39.55) v1(125.32,51.6) v1(128.81,58.81) v1(133.81,53.81)
DGND: length 128.3
  TOP w0.35: P5.11 136.19,20.38 ; P5.11 135.06,19.25 ; P5.11 136.19,18.12 ; P5.11 137.32,19.25 ; DGND.1 92.5,73.48 ; DGND.1 93.57,72.42 ; DGND.1 92.5,71.36 ; DGND.1 91.44,72.42 ; P5.5 133.65,20.38 ; P5.5 133.65,18.12 ; P5.5 132.52,19.25 ; P5.5 134.78,19.25 ; 126.38,12.24 P3.7 ; P3.7 125.26,13.37 ; P3.7 127.51,13.37 ; P3.7 126.38,14.5 ; P2.7 110.75,61.63 ; P2.7 109.62,62.76 ; P2.7 109.62,60.5 ; P2.7 108.49,61.63 ; P2.6 113.29,61.63 ; P2.6 112.16,60.5 ; P2.6 112.16,62.76 ; P2.6 111.03,61.63
  L2_GND w0.35: 108.49,61.63 P2.7 ; P2.7 109.62,62.76 ; P2.7 109.62,60.5 ; P2.7 110.75,61.63 ; 136.19,18.12 P5.11 ; P5.11 137.32,19.25 ; P5.11 135.06,19.25 ; P5.11 136.19,20.38 ; 132.52,19.25 P5.5 ; P5.5 133.65,20.38 ; P5.5 134.78,19.25 ; P5.5 133.65,18.12 ; P2.6 112.16,62.76 ; P2.6 113.29,61.63 ; P2.6 112.16,60.5 ; P2.6 111.03,61.63 ; P3.7 126.38,14.5 ; P3.7 126.38,12.24 ; P3.7 125.26,13.37 ; P3.7 127.51,13.37 ; 91.44,72.42 DGND.1 ; DGND.1 92.5,73.48 ; DGND.1 93.57,72.42 ; DGND.1 92.5,71.36
  L3_SIG w0.35: DGND.1 93.57,72.42 ; DGND.1 92.5,71.36 ; DGND.1 92.5,73.48 ; DGND.1 91.44,72.42 ; 133.65,18.12 P5.5 ; P5.5 133.65,20.38 ; P5.5 132.52,19.25 ; 125.26,13.37 P3.7 ; P3.7 126.38,14.5 ; P3.7 127.51,13.37 ; P2.7 110.75,61.63 ; P2.7 109.62,60.5 ; P2.7 109.62,62.76 ; P2.7 108.49,61.63 ; 136.19,20.38 P5.11 136.19,18.12 ; P2.6 113.29,61.63 ; P2.6 111.03,61.63 ; P2.6 112.16,62.76 ; P2.6 112.16,60.5
  L5_GND w0.35: 133.65,18.12 P5.5 ; P5.5 134.78,19.25 ; P5.5 133.65,20.38 ; P5.5 132.52,19.25 ; P2.7 110.75,61.63 ; P2.7 109.62,60.5 ; P2.7 108.49,61.63 ; P2.7 109.62,62.76 ; 125.26,13.37 P3.7 ; P3.7 126.38,12.24 ; P3.7 126.38,14.5 ; P3.7 127.51,13.37 ; 135.06,19.25 P5.11 ; P5.11 136.19,20.38 ; P5.11 137.32,19.25 ; P5.11 136.19,18.12 ; 91.44,72.42 DGND.1 ; DGND.1 92.5,71.36 ; DGND.1 93.57,72.42 ; DGND.1 92.5,73.48 ; 112.16,60.5 P2.6 ; P2.6 113.29,61.63 ; P2.6 111.03,61.63 ; P2.6 112.16,62.76
  BOTTOM w0.35: P2.6 112.16,62.76 ; P2.6 111.03,61.63 ; P2.6 113.29,61.63 ; P2.6 112.16,60.5 ; 135.06,19.25 P5.11 ; P5.11 136.19,18.12 ; P5.11 137.32,19.25 ; P5.11 136.19,20.38 ; 133.65,18.12 P5.5 ; P5.5 132.52,19.25 ; P5.5 134.78,19.25 ; P5.5 133.65,20.38 ; P2.7 109.62,62.76 ; P2.7 109.62,60.5 ; P2.7 108.49,61.63 ; P2.7 110.75,61.63 ; 91.44,72.42 DGND.1 ; DGND.1 93.57,72.42 ; DGND.1 92.5,73.48 ; DGND.1 92.5,71.36 ; 126.38,12.24 P3.7 ; P3.7 125.26,13.37 ; P3.7 127.51,13.37
  vias: v1(82.69,72.42) v1(83.81,73.81) v1(83.81,63.81) v1(83.81,13.81) v1(83.81,3.81) v1(88.81,68.81) v1(88.81,8.81) v1(93.81,73.81) v1(93.81,63.81) v1(93.81,3.81) v1(95.94,29.36) v1(95.94,24.21) v1(96.94,24.21) v1(98.81,68.81) v1(98.81,18.81) v1(100.33,34.7) v1(100.39,23.49) v1(103.81,73.81) v1(103.81,63.81) v1(103.81,3.81) v1(103.97,26.79) v1(107.47,26.36) v1(108.81,68.81) v1(108.81,28.81) v1(108.81,8.81) v1(113.81,73.81) v1(113.81,63.81) v1(113.81,3.81) v1(118.81,68.81) v1(118.81,28.81) v1(123.81,73.81) v1(123.81,63.81) v1(123.81,3.81) v1(128.81,68.81) v1(128.81,28.81) v1(128.81,8.81) v1(133.81,73.81) v1(133.81,63.81) v1(138.81,68.81) v1(138.81,58.81) v1(138.81,48.81) v1(138.81,38.81) v1(138.81,8.81)
VDD: length 13.5
  TOP w0.5: C18.1 v1(116.86,46.84)
  L4_PWR w0.35: 77.92,63.17 LK3.2 ; LK3.2 76.79,64.3 ; LK3.2 77.92,65.42 ; LK3.2 79.05,64.3 ; 94.75,53.06 TP_VDD.1 ; TP_VDD.1 95.81,54.12 ; TP_VDD.1 93.69,54.12 ; TP_VDD.1 94.75,55.19 ; J9.1 74.94,39.62 ; J9.1 73.06,39.62 ; J9.1 74,40.56 ; J9.1 74,38.69
  vias: v1(103.46,41.8) v1(122.38,45.04)
VSS: length 13.5
  TOP w0.5: C18.2 v1(113.26,46.84)
  L4_PWR w0.35: 90.75,53.06 TP_VSS.1 ; TP_VSS.1 89.69,54.12 ; TP_VSS.1 90.75,55.19 ; TP_VSS.1 91.81,54.12 ; 74,44.71 74,45.64 ; 74,44.71 74.94,44.71 ; 74,44.71 73.06,44.71 ; 74,44.71 74,43.77 ; LK4.2 79.05,55.19 ; LK4.2 77.92,56.31 ; LK4.2 77.92,54.06 ; LK4.2 76.79,55.19
  vias: v1(99.43,38.95) v1(99.43,37.95) v1(99.43,36.95) v1(100.93,38.95) v1(100.93,37.95) v1(100.93,36.95) v1(101.93,34.95) v1(102.43,38.95) v1(102.43,37.95) v1(102.43,36.95) v1(107.78,42.39)
ARD_5V: length 79.9
  L4_PWR w0.35: 47.75,50.51 UNK5V.1 ; UNK5V.1 48.81,51.57 ; UNK5V.1 48.81,49.45 ; UNK5V.1 49.87,50.51 ; LK1.2 110.89,55.25 ; LK1.2 109.83,54.19 ; LK1.2 110.89,53.12 ; LK1.2 111.95,54.19
  BOTTOM w0.5: LK1.2 107.22,50.51 UNK5V.1 46.31,50.51 45.51,51.31 v1(45.51,55.51)
ARD_CLRB: length 116.4
  TOP w0.2: U1.6 99.93,40.49 99.58,40.84 v1(98.21,40.84) 97.51,40.84 97.31,41.05 97.31,41.75
  L3_SIG w0.2: P5.9 135.31,25.21 135.31,26.01 135.01,26.31 135.01,29.91 135.71,30.61 136.71,30.61 138.91,28.41 138.91,13.31 135.41,9.81 97.94,9.81 P4.3
  L3_SIG w0.25: P4.3 93.61,14.14 93.61,38.71 95.75,40.84 v1(98.21,40.84)
  BOTTOM w0.25: P4.3 CLRB.1
ARD_LDACB: length 104.4
  TOP w0.25: U1.7 97.62,40 v1(97.51,40.11) 95.88,41.75 95.78,41.75
  L3_SIG w0.2: 97.01,13.28 99.98,10.31 135.31,10.31 138.41,13.41 138.41,27.19 P5.7
  L3_SIG w0.25: 97.01,13.28 P4.4 94.11,16.18 94.11,38.51 95.91,40.31 97.31,40.31 v1(97.51,40.11)
  BOTTOM w0.25: LDACB.1 96.92,8.46 P4.4
ARD_RESETB: length 92.3
  TOP w0.2: 98.83,41.75 v1(99.63,41.75) ; U1.4 v1(100.93,40.8)
  L3_SIG w0.2: P4.8 109.64,10.81 135.11,10.81 137.91,13.61 137.91,25.15 P5.8
  L3_SIG w0.25: v1(100.93,40.8) 99.98,41.75 v1(99.63,41.75) 99.63,41.03 97.51,38.91 96.91,38.91 96.31,38.31 96.31,31.21 107.08,20.44 P4.8
  BOTTOM w0.25: P4.8 107.06,13.35 RESETB.1
ARD_SCL: length 37.5
  TOP w0.2: U3.6 v1(106.97,25.51)
  BOTTOM w0.2: v1(106.97,25.51) 116.3,25.51 118.3,23.51 118.3,16.8 119.8,15.3 132.07,15.3 P3.10
ARD_SCLK: length 59.6
  TOP w0.2: U1.13 v1(98.58,35.9)
  L3_SIG w0.25: v1(98.58,35.9) 98.58,34.65 99.31,33.91 99.31,30.41 112.61,17.11 120.1,17.11 P3.6 123.84,13.44 132.19,21.79 P5.4
  BOTTOM w0.25: P3.6 123.84,7.38 SCLK.1
ARD_SDA: length 34
  TOP w0.2: U3.5 v1(106.97,24.24)
  BOTTOM w0.2: P3.9 129.93,14.9 119.6,14.9 117.9,16.6 117.9,22.64 116.3,24.24 v1(106.97,24.24)
ARD_SDIN: length 80.1
  TOP w0.2: U1.12 97.18,36.95 v1(96.98,36.75)
  L3_SIG w0.2: P3.4 118.76,13.26 120.71,11.31 134.91,11.31 137.41,13.81 137.41,22.51 136.91,23.01 135.81,23.01 134.91,23.91 134.91,25.61 P5.2
  L3_SIG w0.25: P3.4 116.02,16.11 112.11,16.11 96.98,31.24 v1(96.98,36.75)
  BOTTOM w0.25: SDIN.1 118.76,7.38 P3.4
ARD_SDO: length 74.5
  TOP w0.2: v1(96.98,37.65) 97.18,37.45 U1.11
  L3_SIG w0.2: P5.3 133.79,24.33 135.01,23.11 135.01,15.31 135.61,14.71 135.61,12.71 134.71,11.81 122.86,11.81 P3.5
  L3_SIG w0.25: P3.5 118.06,16.61 112.31,16.61 97.71,31.21 97.71,37.01 97.08,37.65 v1(96.98,37.65)
  BOTTOM w0.25: P3.5 SDO.1
ARD_SYNCB: length 50.7
  TOP w0.2: R9.2 v1(99.42,34.74) 99.93,35.26 U1.14
  TOP w0.25: v1(116.22,19.07) R7.2 R8.2
  L3_SIG w0.25: v1(99.42,34.74) 100.15,34.01 100.71,34.01 115.65,19.07 v1(116.22,19.07) 117.01,19.07 SYNCB.1 127.35,29.41 P5.1
ARD_VLOGIC: length 36.2
  TOP w0.25: C10.1 96.83,38.45 U1.9 ; C10.1 v1(96.58,39.7) ; C10.1 96.83,38.95 U1.8
  TOP w0.5: R12.1 R11.1 R10.1 v1(94.98,43.45) ; R2.1 R1.1 ; R2.1 v1(91.49,26.79) ; R2.1 R3.1 ; E1.2 122.32,54.93 124.55,54.93 C4.1 ; v1(125.32,57.33) C4.1 ; C4.1 129.4,55.7 VLOGIC.1 ; U3.8 C1.2 v1(107.47,28.75) ; R9.1 v1(98.62,32.24)
  L4_PWR w0.35: P5.12 136.19,17.84 ; P5.12 137.32,16.71 ; P5.12 136.19,15.58 ; P5.12 135.06,16.71 ; P5.6 133.65,17.84 ; P5.6 133.65,15.58 ; P5.6 134.78,16.71 ; P5.6 132.52,16.71
DAC_INV: length 16.8
  TOP w0.25: U2.2 113.79,43.73 114.26,43.26 C19.2 v1(113.26,39.34) ; U1.24 v1(104.88,38.95)
  L3_SIG w0.5: v1(104.88,38.95) 112.15,38.95 112.55,39.34 v1(113.26,39.34)
DAC_VOUT: length 46.3
  TOP w0.25: v1(116.86,39.34) C19.1 115.86,41.96 116.36,42.46 U2.6 ; v1(104.88,36.95) U1.20
  L3_SIG w0.5: v1(104.88,36.95) 114.46,36.95 v1(116.86,39.34) 120.28,39.34 124.12,35.49 VOUT_BUFF.1
  BOTTOM w0.5: TP_VOUT_BUFF.1 124.92,35.49 VOUT_BUFF.1
EXT_VDD: length 60.4
  L3_SIG w0.5: LK3.3 71.87,66.83 69.19,69.51 52.81,69.51 52.31,70.01 32.29,70.01 v1(27.9,65.62) v1(26.9,65.62) v1(25.9,65.62) v1(24.9,65.62)
  L4_PWR w0.35: TP_EXT_VDD.1 26.46,58.2 ; TP_EXT_VDD.1 24.34,58.2 ; TP_EXT_VDD.1 25.4,57.14 ; TP_EXT_VDD.1 25.4,59.26
EXT_VSS: length 75
  L3_SIG w0.5: v1(14.9,65.62) v1(15.9,65.62) v1(16.9,65.62) v1(17.9,65.62) 19.41,64.11 29.01,64.11 32.51,67.61 62.71,67.61 63.51,66.81 63.51,64.21 69.42,58.3 75.6,58.3 76.17,57.73 LK4.3
  L4_PWR w0.35: TP_EXT_VSS.1 15.4,59.26 ; TP_EXT_VSS.1 15.4,57.14 ; TP_EXT_VSS.1 16.46,58.2 ; TP_EXT_VSS.1 14.34,58.2
LDO_VDD: length 10.5
  TOP w0.5: TP_LDO_VDD.1 79.27,61.76 LK3.1
  L3_SIG w0.5: LK3.1 76.76,61.76 v1(74.87,63.64)
LDO_VSS: length 14.7
  TOP w0.5: TP_LDO_VSS.1 82.97,52.65 LK4.1
  L3_SIG w0.5: v1(70.06,56.85) 73.71,56.85 LK4.1
REF_VREFN: length 9.6
  BOTTOM w0.5: LK2.1 TP_VREFN.1 J1.3
REF_VREFP: length 58.8
  TOP w0.25: U1.2 101.93,40.53 102.31,40.91 104.11,40.91 v1(104.58,40.45)
  BOTTOM w0.5: v1(104.58,40.45) 104.58,41.75 103.62,42.7 87.1,42.7 79.75,35.35 72.95,35.35 71.51,33.91 71.51,25.71 72.59,24.62 J1.1 TP_VREFP.1
UNNAMED_3_CAP_I71_N1: length 8.9
  TOP w0.5: C5.1 116.93,54.93 114.7,54.93 E2.2 LK1.1
UNNAMED_3_CN8PA_I4_N2: length 3
  TOP w0.5: P2.2 E1.1
UNNAMED_3_CN8PA_I4_N5: length 3
  TOP w0.5: P2.5 E2.1
UNNAMED_3_CN10P_I1_N2: length 3
  TOP w0.2: R8.1 P3.2
UNNAMED_3_CN10P_I1_N3: length 3
  TOP w0.2: R7.1 P3.3
UNNAMED_3_IC24XX32AV2_I22_A0: length 7.2
  TOP w0.25: R3.2 v1(94.94,28.37) ; R6.1 98.09,28.36 v1(98.39,28.05) U3.1
  L3_SIG w0.2: v1(94.94,28.37) 97.52,28.37 97.84,28.05 v1(98.39,28.05)
UNNAMED_3_IC24XX32AV2_I22_A1: length 7
  TOP w0.25: R5.1 v1(98.39,26.79) U3.2 ; R2.2 v1(94.94,26.79)
  L3_SIG w0.2: v1(98.39,26.79) v1(94.94,26.79)
UNNAMED_3_IC24XX32AV2_I22_A2: length 7.2
  TOP w0.25: R1.2 v1(94.94,25.21) ; R4.1 98.09,25.21 v1(98.39,25.51) U3.3
  L3_SIG w0.2: v1(94.94,25.21) 97.54,25.21 97.84,25.51 v1(98.39,25.51)
UNNAMED_4_AD5780_I104_VOUT: length 43.6
  TOP w0.25: U2.3 v1(110.77,42.46) ; U1.1 v1(103.23,40)
  L3_SIG w0.25: v1(103.23,40) 104.35,41.11 109.42,41.11 v1(110.77,42.46) 121.46,42.46 125.5,46.5 VOUT.1
  BOTTOM w0.5: VOUT.1 124.92,46.5 TP_VOUT.1
UNNAMED_4_AD5780_I104_VREFN: length 23
  TOP w0.2: v1(101.38,31.24) 100.93,31.69 U1.16
  BOTTOM w0.5: v1(101.38,31.24) 86.48,31.24 85.48,32.24 LK2.2
UNNAMED_5_ADP5070_I73_COMP1: length 3.9
  TOP w0.25: R26.1 C23.1 39.8,60.8 40.44,60.16 U4.6
UNNAMED_5_ADP5070_I73_COMP2: length 3.9
  TOP w0.25: U4.10 40.44,57.64 39.76,56.96 C25.1 R27.1
UNNAMED_5_ADP5070_I73_EN1: length 17.2
  TOP w0.25: R14.1 R15.2 v1(47.16,52.45) ; U4.7 39.78,59.38 v1(39.36,59.8) ; U4.9 39.86,58.38 v1(39.36,57.88)
  L3_SIG w0.25: v1(47.16,52.45) 43.97,52.45 39.36,57.06 v1(39.36,57.88) v1(39.36,59.8)
UNNAMED_5_ADP5070_I73_FB1: length 7
  TOP w0.25: U4.5 40.4,60.9 39.51,61.79 39.51,64.8 R25.1 R24.1
UNNAMED_5_ADP5070_I73_FB2: length 3.6
  TOP w0.25: R29.1 R28.2 40.05,55.95 40.2,56.1 41.1,56.1 41.46,56.46 U4.11
UNNAMED_5_ADP5070_I73_SEQ: length 5.9
  TOP w0.2: R22.1 v1(42.46,65.25)
  TOP w0.25: U4.3 v1(42.46,61.9) R19.2
  L3_SIG w0.25: v1(42.46,65.25) v1(42.46,61.9)
UNNAMED_5_ADP5070_I73_SLEW: length 6.7
  TOP w0.2: R21.1 v1(40.96,65.25)
  TOP w0.25: R18.2 v1(40.96,61.9) 41.62,61.9 41.96,61.56 U4.4
  L3_SIG w0.25: v1(40.96,65.25) v1(40.96,61.9)
UNNAMED_5_ADP5070_I73_SS: length 1.9
  TOP w0.25: U4.8 R16.2
UNNAMED_5_ADP5070_I73_SW2: length 3.3
  TOP w0.25: U4.18 47.78,58.88
UNNAMED_5_ADP5070_I73_SYNC: length 6.6
  TOP w0.2: R20.1 v1(43.96,65.25)
  TOP w0.25: U4.2 42.96,61.46 43.4,61.9 v1(43.96,61.9) R17.2
  L3_SIG w0.25: v1(43.96,65.25) v1(43.96,61.9)
UNNAMED_5_ADP5070_I73_VREF: length 3.3
  TOP w0.25: C27.1 41.05,54.35 R28.1 41.96,56.27 U4.12
UNNAMED_5_ADP5070_I73_VREG: length 18.7
  TOP w0.2: v1(44.46,55.11) C35.1 42.96,55.81 U4.14 ; v1(40.16,64.35) R18.1 R19.1 R17.1
  L3_SIG w0.25: v1(44.46,55.11) 43.16,56.41 41.31,56.41 40.16,57.56 v1(40.16,64.35)
UNNAMED_5_ADP7118V3_I134_EN: length 3.2
  L3_SIG w0.5: v1(64.79,68.31) v1(64.79,65.13)
UNNAMED_5_ADP7182V5_I135_ADJ: length 5.2
  TOP w0.2: R35.2 R36.1 73.31,56.49 72.89,56.91 71.39,56.91 71.06,57.24 U6.2
UNNAMED_5_CAP_I98_N1: length 23.2
  TOP w0.25: R24.2 v1(37.41,66.3)
  L3_SIG w0.25: v1(37.41,66.3) v1(59.89,66.3)
UNNAMED_5_CAP_I106_N1: length 1.4
  TOP w0.25: C24.1 R26.2
UNNAMED_5_CAP_I110_N1: length 1.4
  TOP w0.25: R27.2 C26.1
UNNAMED_5_CAP_I118_N1: length 30.3
  TOP w0.25: R29.2 v1(40.05,52.64)
  L3_SIG w0.25: v1(66.46,58.6) 59.67,51.81 40.88,51.81 v1(40.05,52.64)
UNNAMED_5_CN3P_I182_N1: length 3.6
  TOP w0.35: P6.1 20.1,71.61 ; P6.1 21.29,70.42 ; P6.1 20.1,69.23
UNNAMED_5_CN3P_I182_N3: length 3.6
  TOP w0.35: P6.3 10.09,71.61 ; P6.3 11.28,70.42 ; P6.3 10.09,69.23

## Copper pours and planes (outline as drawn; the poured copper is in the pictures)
AGND on TOP: 0.5,74.5 80.5,74.5 80.5,61.11 82.11,59.5 135.51,59.5 135.51,31.31 125.11,31.31 101.61,31.31 101.28,31.63 101.28,32.91 103.01,32.91 103.01,35.06 102.53,35.54 102.53,36.76 98.35,36.76 90.01,28.42 90.01,16.4 80.5,16.4 80.5,0.5 0.5,0.5 ; 2 cut-outs
AGND on BOTTOM: 0.5,74.5 80.5,74.5 80.5,59.5 135.51,59.5 135.51,31.31 101.11,31.31 101.11,36.91 98.51,36.91 90.01,28.41 90.01,16.4 80.5,16.4 80.5,0.5 0.5,0.5
AGND on L2_GND: 0.5,74.5 80.5,74.5 80.5,59.5 135.51,59.5 135.51,31.31 101.81,31.31 101.11,32 101.11,36.9 98.49,36.9 90.01,28.42 90.01,16.4 80.5,16.4 80.5,0.5 0.5,0.5
AGND on L4_PWR: 0.5,74.5 32.4,74.5 32.4,33 87.21,33 87.21,20.31 125.41,20.31 125.41,0.5 0.5,0.5
AGND on L5_GND: 0.5,74.5 80.5,74.5 80.5,59.5 135.51,59.5 135.51,31.31 101.11,31.31 101.11,36.9 98.5,36.9 90.01,28.41 90.01,16.41 80.5,16.41 80.5,0.5 0.5,0.5
DGND on TOP: 81.01,74.5 139.5,74.5 139.5,0.5 81.01,0.5 81.01,15.9 90.51,15.9 90.51,28.21 98.81,36.51 100.61,36.51 100.61,31.31 101.11,30.81 136.01,30.81 136.01,60 82.02,60 81.01,61.01
DGND on BOTTOM: 81,74.5 139.5,74.5 139.5,0.5 81,0.5 81,15.9 90.51,15.9 90.51,28.21 98.71,36.41 100.61,36.41 100.61,31.31 101.12,30.8 101.36,30.81 136.01,30.81 136.01,60 81,60
DGND on L2_GND: 81,74.5 139.5,74.5 139.5,0.5 81,0.5 81,15.9 90.51,15.9 90.51,28.21 98.7,36.4 100.61,36.4 100.61,31.31 101.11,30.81 136.01,30.81 136.01,60 81,60
DGND on L3_SIG: 0.5,74.5 139.5,74.5 139.5,0.5 0.5,0.5 ; 9 cut-outs
DGND on L5_GND: 81,74.5 139.5,74.5 139.5,0.5 81,0.5 81,15.91 90.51,15.91 90.51,28.21 98.7,36.4 100.61,36.4 100.61,31.31 101.11,30.81 136.01,30.81 136.01,60 81,60
VDD on TOP: 116.41,44.45 116.41,43.05 124.11,43.05 124.11,45.34 121.64,45.34 120.75,44.45
VDD on TOP: 100.18,42.61 103.61,42.61 103.81,42.41 103.81,40.91 103.64,40.74 101.77,40.74 101.64,40.61 101.64,39.45 100.18,39.45
VDD on L4_PWR: 66.6,67.6 66.6,33.51 75.3,33.51 75.3,42.01 72.31,42.01 72.31,58.31 93.01,58.31 93.01,45.11 100.41,45.11 100.41,41.5 103.71,41.5 103.71,49.71 119.01,49.71 119.01,58.5 126.11,58.5 126.11,47.11 116.61,47.11 116.61,33.51 139.5,33.51 139.5,74.5 112.71,74.5 112.71,52.4 99.8,52.4 99.8,67.6
VSS on TOP: 99.13,39.25 102.74,39.25 102.74,36.64 102.27,36.64 102.03,36.4 102.03,35.34 102.51,34.86 102.51,33.41 101.33,33.41 101.33,36.4 101.1,36.64 99.13,36.64
VSS on TOP: 113.61,41.84 113.61,40.34 106.04,40.34 106.04,42.65 109.87,42.65 110.67,41.84
VSS on L4_PWR: 66.6,41.9 66.6,33.5 113.51,33.5 113.51,47.11 106.21,47.11 106.21,38.21 102.91,38.21 102.91,39.21 99.01,39.21 99.01,38.21 92.5,38.21 92.51,39.16 92.51,57.81 73.21,57.81 72.81,57.41 72.81,42.71 75.8,42.71 75.8,41.9
ARD_5V on TOP: 44,58.45 44,57.3 43.3,57.3 43.3,55.9 44.4,55.9 45.5,54.8 46.9,54.8 46.9,58.45
ARD_5V on L4_PWR: 32.7,74.5 32.7,33.5 66.1,33.5 66.1,68.1 100.3,68.1 100.3,52.9 112.21,52.9 112.21,74.5
ARD_VLOGIC on L4_PWR: 93.01,44.61 93.01,38.71 98.51,38.71 98.51,39.71 103.41,39.71 103.41,38.71 105.71,38.71 105.71,47.61 114.01,47.61 114.01,33.01 87.71,33.01 87.71,20.81 125.91,20.81 125.91,0.5 139.5,0.5 139.5,33.01 116.11,33.01 116.11,47.61 125.61,47.61 125.61,58.01 119.51,58.01 119.51,49.21 104.21,49.21 104.21,41.01 99.91,41.01 99.91,44.61
EXT_VDD on TOP: 22.1,66 22.1,63.6 28.7,63.6 28.7,66
EXT_VDD on L4_PWR: 22.1,66 22.1,55.7 28.7,55.7 28.7,66
EXT_VSS on TOP: 12.09,66 12.09,63.6 18.69,63.6 18.69,66
EXT_VSS on L4_PWR: 12.09,66 12.09,55.7 18.69,55.7 18.69,66
LDO_VDD on TOP: 70.5,66.2 70.5,62.7 75.2,62.7 75.2,64.6 74.2,64.6 74,64.8 74,66.2
LDO_VSS on TOP: 70.2,58.1 70.2,57.4 69.5,56.7 68.9,56.7 68.9,55.1 72.2,55.1 72.2,56.7 71.3,56.7 70.6,57.4 70.6,58.1
UNNAMED_5_ADP5070_I73_INBK on TOP: 43.3,61.4 43.3,60.4 43.7,60.4 44.1,60.8 46.9,60.8 48.3,62.2 48.3,70.6 45,70.6 45,62.2 44.2,61.4
UNNAMED_5_ADP5070_I73_SW1 on TOP: 44,60.3 44,59.8 48.8,59.8 50.6,61.6 54.3,61.6 54.3,63.6 52.8,63.6 51.8,64.6 51.8,70.6 48.6,70.6 48.6,62.1 47,60.5 44.2,60.5
UNNAMED_5_ADP5070_I73_SW2 on TOP: 44,59.05 44,58.7 57.1,58.7 57.1,61.35 50.75,61.35 48.9,59.5 45.5,59.5 45.05,59.05
UNNAMED_5_ADP7118V3_I134_EN on TOP: 66.8,69.1 66.8,67.7 61.7,67.7 61.7,69.1
UNNAMED_5_ADP7118V3_I134_EN on TOP: 64.5,65.9 64.5,63.7 64.7,63.5 66.8,63.5 66.8,66.1 64.7,66.1
UNNAMED_5_ADP7118V3_I134_SENSE on TOP: 70.5,67.7 70.5,66.5 75.5,66.5 75.5,67.7
UNNAMED_5_ADP7118V3_I134_SS on TOP: 66.8,67.4 66.8,66.4 64.6,66.4 64.3,66.1 63.2,66.1 63.2,67.4
UNNAMED_5_ADP7182V5_I135_EN on TOP: 67.8,62.2 67.8,59.4 69.2,59.4 70.2,58.4 71.3,58.4 71.5,58.2 71.5,57.3 71.9,57.3 71.9,59.2 70.9,59.2 70.6,59.5 70.6,62.2
UNNAMED_5_CAP_I94_N1 on TOP: 52.1,70.6 52.1,64.7 52.9,63.9 54.6,63.9 54.6,61.6 57.1,61.6 57.1,70.6
UNNAMED_5_CAP_I98_N1 on TOP: 57.4,70.6 57.4,62.5 61.2,62.5 61.2,70.6
UNNAMED_5_CAP_I117_N1 on TOP: 62.3,62.2 62.3,56.2 57.4,56.2 57.4,62.2
